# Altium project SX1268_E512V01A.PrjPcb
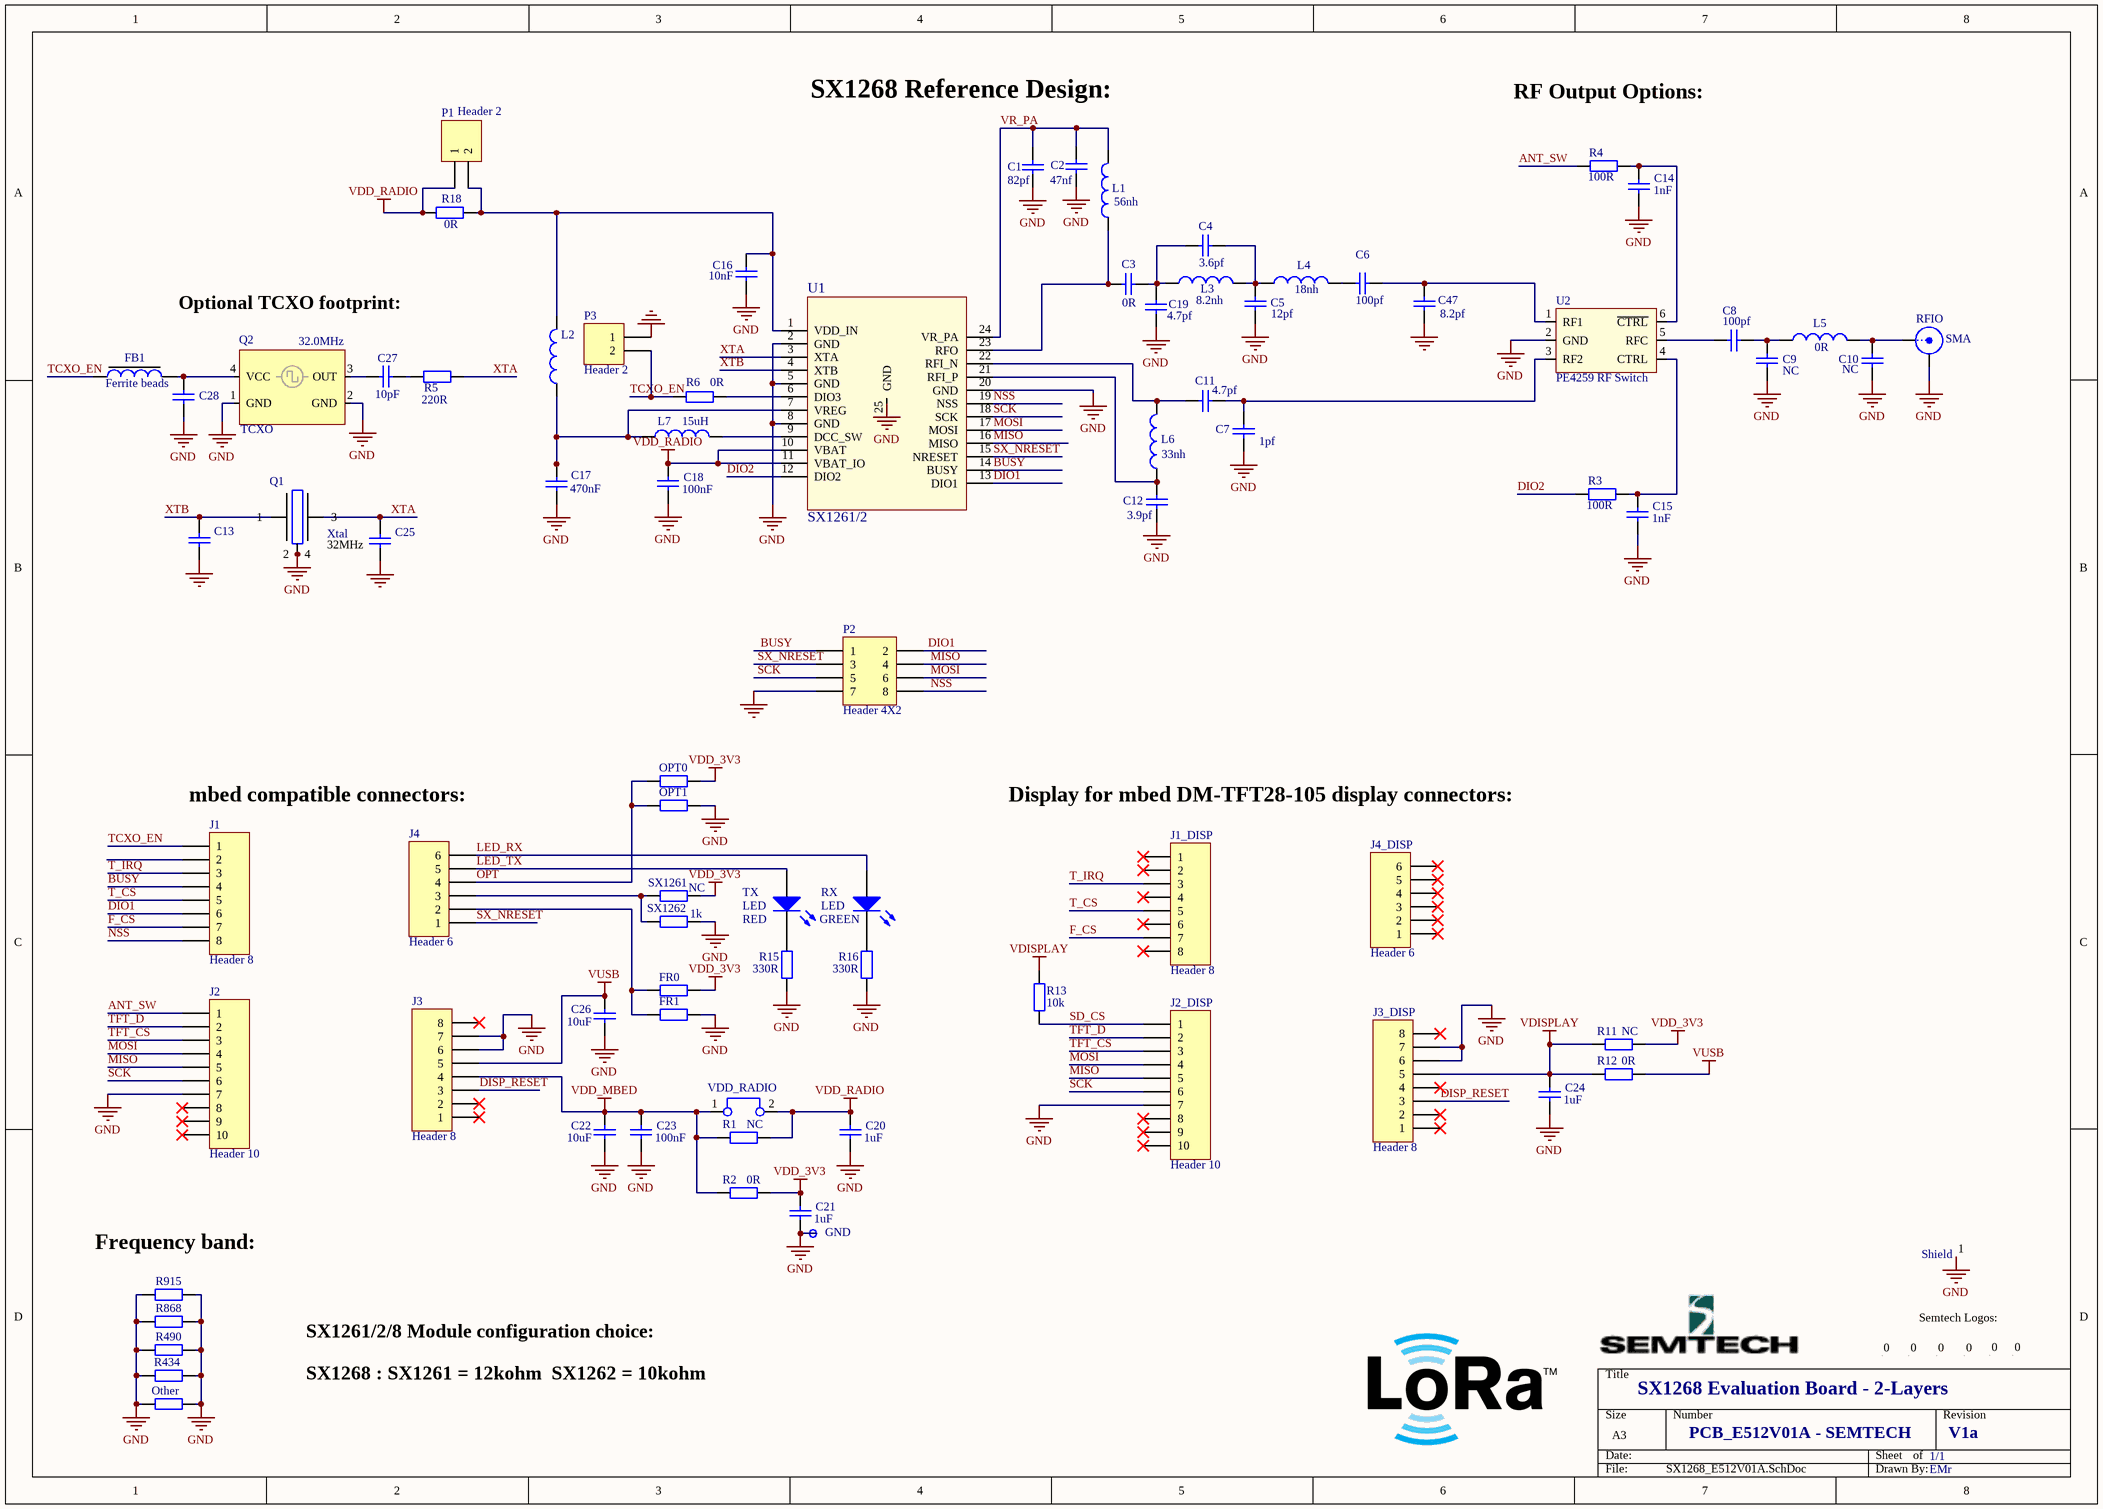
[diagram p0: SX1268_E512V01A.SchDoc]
1 sheet, 87 parts. Net scope: global (net labels, ports and power ports of the same name join across sheets).
Board file: SX1268_E512V01A.PcbDoc

## Sheet SX1268_E512V01A.SchDoc
size A3; DocumentNumber: 1; SheetNumber: 1; SheetTotal: 2

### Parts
C1  value 82pf  [rlc_402_smd]  (hidden comment: Cap)
C2  value 47nf  [rlc_402_smd]  (hidden comment: Cap)
C3  value 0R  [rlc_402_smd]  (hidden comment: Cap)
C4  value 3.6pf  [rlc_402_smd]  (hidden comment: Cap)
C5  value 12pf  [rlc_402_smd]  (hidden comment: Cap)
C6  value 100pf  [rlc_402_smd]  (hidden comment: Cap)
C7  value 1pf  [rlc_402_smd]  (hidden comment: Cap)
C8  value 100pf  [rlc_402_smd]  (hidden comment: Cap)
C9  value NC  [rlc_402_smd]  (hidden comment: Cap)
C10  value NC  [rlc_402_smd]  (hidden comment: Cap)
C11  value 4.7pf  [rlc_402_smd]  (hidden comment: Cap)
C12  value 3.9pf  [rlc_402_smd]  (hidden comment: Cap)
C13  Cap  [rlc_402_smd]  (value not drawn)
C14  value 1nF  [rlc_402_smd]  (hidden comment: Cap)
C15  value 1nF  [rlc_402_smd]  (hidden comment: Cap)
C16  value 10nF  [rlc_402_smd]  (hidden comment: Cap)
C17  value 470nF  [rlc_402_smd]  (hidden comment: Cap)
C18  value 100nF  [rlc_402_smd]  (hidden comment: Cap)
C19  value 4.7pf  [rlc_402_smd]  (hidden comment: Cap)
C20  value 1uF  [rlc_603_smd]  (hidden comment: Cap)
C21  value 1uF  [rlc_603_smd]  (hidden comment: Cap)
C22  value 10uF  [rlc_805_smd]  (hidden comment: Cap)
C23  value 100nF  [rlc_402_smd]  (hidden comment: Cap)
C24  value 1uF  [rlc_402_smd]  (hidden comment: Cap)
C25  Cap  [rlc_402_smd]  (value not drawn)
C26  value 10uF  [rlc_805_smd]  (hidden comment: Cap)
C27  value 10pF  [rlc_402_smd]  (hidden comment: Cap)
C28  Cap  [rlc_402_smd]  (value not drawn)
C47  value 8.2pf  [rlc_402_smd]  (hidden comment: Cap)
FB1  Ferrite beads  [rlc_402_smd]
FR0  Resistor  [rlc_402_smd]  (value not drawn)
FR1  Resistor  [rlc_402_smd]  (value not drawn)
GND  Test Pin  [pin_0.9mm]  (value not drawn)
J1  Header 8  [HDR1X8]
J1_DISP  Header 8  [HDR1X8]
J2  Header 10  [HDR1X10]
J2_DISP  Header 10  [HDR1X10]
J3  Header 8  [HDR1X8]
J3_DISP  Header 8  [HDR1X8]
J4  Header 6  [HDR1X6]
J4_DISP  Header 6  [HDR1X6]
L1  value 56nh  [rlc_402_smd]  (hidden comment: Inductor)
L2  Inductor  [rlc_402_smd]  (value not drawn)
L3  value 8.2nh  [rlc_402_smd]  (hidden comment: Inductor)
L4  value 18nh  [rlc_402_smd]  (hidden comment: Inductor)
L5  value 0R  [rlc_402_smd]  (hidden comment: Inductor)
L6  value 33nh  [rlc_402_smd]  (hidden comment: Inductor)
L7  value 15uH  [rlc_805_smd enlarged]  (hidden comment: Inductor)
Logo_Bot  Logo symbol  [logo_semtech_horiz_size4]  (value not drawn)
Logo_ESD  Logo symbol  [Logo ESD]  (value not drawn)
Logo_LoRA1  Logo symbol  [Logo LoRa Size4]  (value not drawn)
Logo_LoRA2  Logo symbol  [Logo LoRa Size3]  (value not drawn)
Logo_Recycling1  Logo symbol  [Logo Recycling1]  (value not drawn)
Logo_Semtech_S  Logo symbol  [logo_semtech_horiz_size3]  (value not drawn)
OPT0  Resistor  [rlc_402_smd]  (value not drawn)
OPT1  Resistor  [rlc_402_smd]  (value not drawn)
Other  Resistor  [rlc_402_smd]  (value not drawn)
P1  Header 2  [HDR1X2]
P2  Header 4X2  [HDR2X4]
P3  Header 2  [HDR1X2]
Q1  Xtal  value 32MHz  [nd2520da]
Q2  TCXO  value 32.0MHz  [TCXO 2.0x1.6mm]
R1  value NC  [rlc_603_smd]  (hidden comment: Resistor)
R2  value 0R  [rlc_603_smd]  (hidden comment: Resistor)
R3  value 100R  [rlc_402_smd]  (hidden comment: Resistor)
R4  value 100R  [rlc_402_smd]  (hidden comment: Resistor)
R5  value 220R  [rlc_402_smd]  (hidden comment: Resistor)
R6  value 0R  [rlc_402_smd]  (hidden comment: Resistor)
R11  value NC  [rlc_402_smd]  (hidden comment: Resistor)
R12  value 0R  [rlc_402_smd]  (hidden comment: Resistor)
R13  value 10k  [rlc_402_smd]  (hidden comment: Resistor)
R15  value 330R  [rlc_402_smd]  (hidden comment: Resistor)
R16  value 330R  [rlc_402_smd]  (hidden comment: Resistor)
R18  value 0R  [rlc_402_smd]  (hidden comment: Resistor)
R434  Resistor  [rlc_402_smd]  (value not drawn)
R490  Resistor  [rlc_402_smd]  (value not drawn)
R868  Resistor  [rlc_402_smd]  (value not drawn)
R915  Resistor  [rlc_402_smd]  (value not drawn)
RFIO  SMA  [SMA_end_launch_1.0mm_9.52mm]
RX  LED  value GREEN  [LGM676 LED]
Shield  Logo symbol  [BMIS-209-F - Shield]  (value not drawn)
SX1261  value NC  [rlc_402_smd]  (hidden comment: Resistor)
SX1262  value 1k  [rlc_402_smd]  (hidden comment: Resistor)
TX  LED  value RED  [LGM676 LED]
U1  SX1261/2  [vqfn24_4x4mm]
U2  PE4259 RF Switch  [SC70-6]
VDD_RADIO  Jumper  [bridge_254mm]  (value not drawn)

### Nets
GND: C1.1 C2.1 C5.1 C7.1 C9.1 C10.1 C12.1 C13.1 C14.2 C15.2 C16.1 C17.1 C18.1 C19.2 C20.1 C21.1 C22.1 C23.1 C24.1 C25.1 C26.1 C28.1 C47.1 FR1.1 GND.1(pin) J2.7 J2_DISP.7 J3.6 J3.7 J3_DISP.6 J3_DISP.7 OPT1.1 Other.1 Other.2 P2.7 P3.1 Q1.2 Q1.4 Q2.1(GND) Q2.2(GND) R15.1 R16.1 R434.1 R434.2 R490.1 R490.2 R868.1 R868.2 R915.1 R915.2 RFIO.2(GND) Shield.1 SX1262.1 U1.2(GND) U1.5(GND) U1.8(GND) U1.20(GND) U1.25(GND) U2.2(GND)
VDD_3V3: C21.2 FR0.1 OPT0.1 R2.1 R11.1 SX1261.1
VDD_MBED: C22.2 C23.2 J3.4 R1.2 R2.2 VDD_RADIO.1
VDD_RADIO: C18.2 C20.2 P1.1 R1.1 R18.2 U1.10(VBAT) U1.11(VBAT_IO) VDD_RADIO.2
VDISPLAY: C24.2 J3_DISP.5 R11.2 R12.2 R13.1
VUSB: C26.2 J3.5 R12.1
ANT_SW: J2.1 R4.2
BUSY: J1.4 P2.1 U1.14(BUSY)
DIO1: J1.6 P2.2 U1.13(DIO1)
DIO2: R3.2 U1.12(DIO2)
DISP_RESET: J3.3 J3_DISP.3
F_CS: J1.7 J1_DISP.7
LED_RX: J4.6 RX.1(A)
LED_TX: J4.5 TX.1(A)
MISO: J2.5 J2_DISP.5 P2.4 U1.16(MISO)
MOSI: J2.4 J2_DISP.4 P2.6 U1.17(MOSI)
NSS: J1.8 P2.8 U1.19(NSS)
OPT: J4.4 OPT0.2 OPT1.2
SCK: J2.6 J2_DISP.6 P2.5 U1.18(SCK)
SD_CS: J2_DISP.1 R13.2
SX_NRESET: J4.1 P2.3 U1.15(NRESET)
T_CS: J1.5 J1_DISP.5
T_IRQ: J1.3 J1_DISP.3
TCXO_EN: FB1.1 J1.1 P3.2 R6.1
TFT_CS: J2.3 J2_DISP.3
TFT_D: J2.2 J2_DISP.2
VR_PA: C1.2 C2.2 L1.2 U1.24(VR_PA)
XTA: C25.2 Q1.3 R5.2 U1.3(XTA)
XTB: C13.2 Q1.1 U1.4(XTB)
NetC3_1: C3.1 C4.2 C19.1 L3.1
NetC3_2: C3.2 L1.1 U1.23(RFO)
NetC4_1: C4.1 C5.2 L3.2 L4.1
NetC6_1: C6.1 C47.2 U2.1(RF1)
NetC6_2: C6.2 L4.2
NetC7_2: C7.2 C11.1 U2.3(RF2)
NetC8_1: C8.1 C9.2 L5.1
NetC8_2: C8.2 U2.5(RFC)
NetC10_2: C10.2 L5.2 RFIO.1(Signal)
NetC11_2: C11.2 L6.2 U1.22(RFI_N)
NetC12_2: C12.2 L6.1 U1.21(RFI_P)
NetC14_1: C14.1 R4.1 U2.6(~{CTRL})
NetC15_1: C15.1 R3.1 U2.4(CTRL)
NetC16_2: C16.2 L2.2 P1.2 R18.1 U1.1(VDD_IN)
NetC17_2: C17.2 L2.1 L7.1 U1.7(VREG)
NetC27_1: C27.1 Q2.3(OUT)
NetC27_2: C27.2 R5.1
NetC28_2: C28.2 FB1.2 Q2.4(VCC)
NetFR0_2: FR0.2 FR1.2 J4.2
NetJ4_3: J4.3 SX1261.2 SX1262.2
NetL7_2: L7.2 U1.9(DCC_SW)
NetR6_2: R6.2 U1.6(DIO3)
NetR15_2: R15.2 TX.2(K)
NetR16_2: R16.2 RX.2(K)

Not connected (* = marked no-connect by the designer): J1 2; J1_DISP 1* 2* 4* 6* 8*; J2 8* 9* 10*; J2_DISP 8* 9* 10*; J3 1* 2* 8*; J3_DISP 1* 2* 4* 8*; J4_DISP 1* 2* 3* 4* 5* 6*; Logo_Bot 0; Logo_ESD 0; Logo_LoRA1 0; Logo_LoRA2 0; Logo_Recycling1 0; Logo_Semtech_S 0

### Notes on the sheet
- SX1268 Reference Design:
- RF Output Options:
- Optional TCXO footprint:
- mbed compatible connectors:
- Display for mbed DM-TFT28-105 display connectors:
- (near R915) Frequency band:
- Semtech Logos:
- SX1268 : SX1261 = 12kohm  SX1262 = 10kohm
- SX1261/2/8 Module configuration choice:
- SX1268 Evaluation Board - 2-Layers
- PCB_E512V01A - SEMTECH
- 1/1
- V1a
- EMr

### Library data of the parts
C1-C27 C47 = Cap: Capacitor SMD
C28 = Cap: Capacitor SMD; Value: 100nF
FB1 = Ferrite beads: Value: NC
FR0 OPT0 = Resistor: Resistor SMD - IEC symbol version; Value: 1k
FR1 OPT1 Other R434 R490 R868 R915 = Resistor: Resistor SMD - IEC symbol version; Value: NC
GND = test_pin
J1 J1_DISP J3 J3_DISP = Header 8: Header, 8-Pin
J2 J2_DISP = Header 10: Header, 10-Pin
J4 J4_DISP = Header 6: Header, 6-Pin
L1 L3-L7 = Inductor: Inductor SMD; Code_IEC: 1005
L2 = Inductor: Inductor SMD; Code_IEC: 1005; Value: 48uH
Logo_Bot Logo_ESD Logo_LoRA1 Logo_LoRA2 Logo_Recycling1 Logo_Semtech_S = Logo: Schematic symbol for Logo
P1 P3 = Header 2: Header, 2-Pin
P2 = Header 4X2: Header, 4-Pin, Dual row
Q1 = Xtal GND: Crystal with GND pins; 4 pins
R1-R6 R11-R13 R15 R16 R18 SX1261 SX1262 = Resistor: Resistor SMD - IEC symbol version
RFIO = SMA: SMA Straight Connector
Shield = Shield: Shield - EMI Gasket - Standard Surface Mount Shields
U1 = SX126x: SX1261/2 - Ultra low power RF transceiver
U2 = PE4259 RF Switch: PE4259 Peregrine RF Switch
VDD_RADIO = Jumper: Jumper Wire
